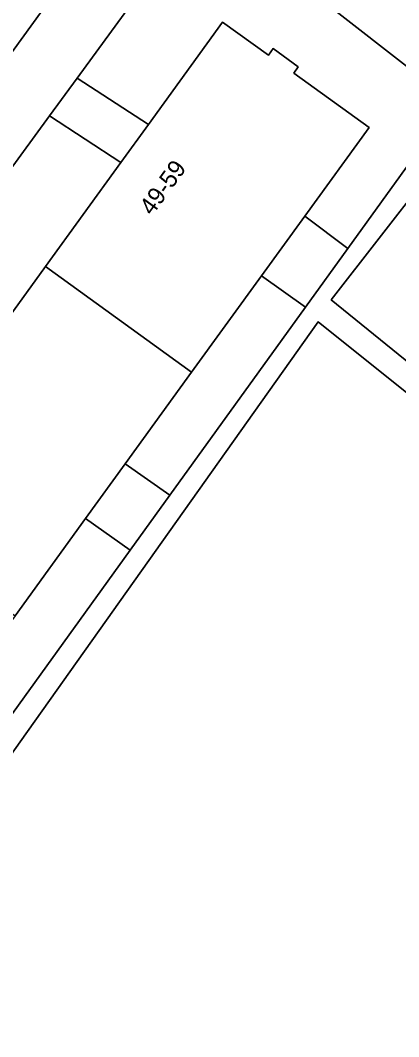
# Model space of a CAD drawing. Extents: x 160102 to 160934, y 382045 to 382923.
# Drawn here: x 160420.9 to 160442.6, y 382523.7 to 382582.2 of the extents above; entities that cross this region are included whole.
import ezdxf

# ---------------------------------------------------------------- set-up
doc = ezdxf.new("R2010")
doc.units = 0
for name, color, linetype in [('IMGEO_Groenvoorziening', 7, 'Continuous'), ('IMGEO_Pand', 7, 'Continuous'), ('IMGEO_Pand_nummerreeks', 7, 'Continuous'), ('IMGEO_Rijbaan_lokaal_open', 7, 'Continuous'), ('IMGEO_Voetpad_op_trap', 7, 'Continuous'), ('IMGEO_Voetpad_open', 7, 'Continuous')]:
    doc.layers.add(name, color=color, linetype=linetype)

msp = doc.modelspace()

# ---------------------------------------------------------------- linework, layer by layer
at = {"layer": 'IMGEO_Groenvoorziening'}
for points in [[(160430.115, 382587.054), (160424.126, 382578.857), (160428.223, 382576.184), (160432.492, 382582.073), (160435.12, 382580.168), (160435.4, 382580.554), (160436.844, 382579.507), (160436.581, 382579.143), (160440.91, 382576.005), (160437.214, 382570.907), (160439.693, 382569.052), (160445.752, 382577.45), (160433.113, 382587.311)], [(160472.07, 382537.55), (160437.989, 382564.836), (160403.791, 382516.657), (160410.005, 382512.232), (160410.556, 382511.838), (160413.843, 382516.2), (160417.933, 382521.84), (160420.393, 382520.056), (160422.852, 382518.273), (160425.312, 382516.489), (160427.772, 382514.705), (160430.232, 382512.922), (160432.692, 382511.138), (160435.152, 382509.354), (160437.611, 382507.571), (160440.071, 382505.787), (160442.541, 382503.996), (160439.632, 382500), (160438.441, 382498.363), (160435.401, 382494.048), (160435.774, 382493.781)]]:
    msp.add_lwpolyline(points, dxfattribs=at)
for points in [[(160448.284, 382571.507), (160448.623, 382571.236), (160450.605, 382573.72), (160456.375, 382569.115), (160459.072, 382572.243), (160450.852, 382578.804), (160448.152, 382575.578), (160446.881, 382576.57), (160438.73, 382566.096), (160447.552, 382558.944), (160449.558, 382561.251), (160444.105, 382565.604), (160447.497, 382569.854), (160447.172, 382570.113)], [(160426.646, 382574.008), (160422.539, 382576.683), (160413.97, 382564.954), (160418.113, 382562.237), (160422.306, 382568.021)], [(160437.257, 382565.676), (160434.732, 382567.482), (160430.709, 382561.932), (160426.893, 382556.667), (160429.461, 382554.871)], [(160427.176, 382551.704), (160424.614, 382553.524), (160420.556, 382547.925), (160416.873, 382542.845), (160419.461, 382541.01)]]:
    msp.add_lwpolyline(points, close=True, dxfattribs=at)
at = {"layer": 'IMGEO_Pand'}
for points in [[(160440.91, 382576.005), (160436.581, 382579.143), (160436.844, 382579.507), (160435.4, 382580.554), (160435.12, 382580.168), (160432.492, 382582.073), (160428.223, 382576.184), (160426.646, 382574.008), (160422.306, 382568.021), (160430.709, 382561.932), (160434.732, 382567.482), (160437.214, 382570.907)], [(160430.709, 382561.932), (160422.306, 382568.021), (160418.113, 382562.237), (160416.492, 382560), (160412.153, 382554.014), (160420.556, 382547.925), (160424.614, 382553.524), (160426.893, 382556.667)]]:
    msp.add_lwpolyline(points, close=True, dxfattribs=at)
at = {"layer": 'IMGEO_Rijbaan_lokaal_open'}
msp.add_lwpolyline([(160391.646, 382540.752), (160393.41, 382543.181), (160399.927, 382552.158), (160401.681, 382554.574), (160406.461, 382561.166), (160408.188, 382563.548), (160411.227, 382567.738), (160412.981, 382570.158), (160416.676, 382575.255), (160418.415, 382577.656), (160424.094, 382585.479), (160425.903, 382587.906), (160426.45, 382588.641), (160422.43, 382591.723), (160415.332, 382581.933), (160382.519, 382536.771), (160386.546, 382533.67)], close=True, dxfattribs=at)
at = {"layer": 'IMGEO_Voetpad_op_trap'}
for points in [[(160439.693, 382569.052), (160437.214, 382570.907), (160434.732, 382567.482), (160437.257, 382565.676)], [(160429.461, 382554.871), (160426.893, 382556.667), (160424.614, 382553.524), (160427.176, 382551.704)]]:
    msp.add_lwpolyline(points, close=True, dxfattribs=at)
at = {"layer": 'IMGEO_Voetpad_open'}
for points in [[(160402.258, 382548.922), (160403.833, 382551.078), (160412.434, 382562.851), (160413.97, 382564.954), (160422.539, 382576.683), (160424.126, 382578.857), (160430.115, 382587.054), (160435.406, 382595.933), (160432.912, 382597.37)], [(160433.113, 382587.311), (160445.752, 382577.45), (160446.881, 382576.57), (160448.152, 382575.578), (160450.852, 382578.804), (160459.072, 382572.243), (160461.271, 382570.488), (160472.502, 382561.524), (160474.597, 382559.852), (160480.93, 382554.797), (160484.046, 382558.32), (160483.799, 382558.523)], [(160424.094, 382585.479), (160418.415, 382577.656), (160419.887, 382576.604), (160418.163, 382574.192), (160416.676, 382575.255), (160412.981, 382570.158), (160414.463, 382569.08), (160412.705, 382566.663), (160411.227, 382567.738), (160408.188, 382563.548), (160409.648, 382562.496), (160407.928, 382560.109), (160406.461, 382561.166), (160401.681, 382554.574), (160403.149, 382553.526), (160401.414, 382551.096), (160399.927, 382552.158), (160393.41, 382543.181), (160394.877, 382542.108), (160393.106, 382539.685), (160391.646, 382540.752), (160386.546, 382533.67)], [(160445.752, 382577.45), (160439.693, 382569.052), (160437.257, 382565.676), (160429.461, 382554.871), (160427.176, 382551.704), (160419.461, 382541.01), (160417.265, 382537.967), (160409.286, 382526.908), (160407.104, 382523.884), (160403.7, 382519.166), (160402.184, 382517.802), (160403.791, 382516.657), (160437.989, 382564.836), (160472.07, 382537.55)], [(160447.552, 382558.944), (160438.73, 382566.096), (160446.881, 382576.57)]]:
    msp.add_lwpolyline(points, dxfattribs=at)
msp.add_lwpolyline([(160428.223, 382576.184), (160424.126, 382578.857), (160422.539, 382576.683), (160426.646, 382574.008)], close=True, dxfattribs=at)

# ---------------------------------------------------------------- texts
at = {"layer": 'IMGEO_Pand_nummerreeks'}
msp.add_text('49-59', height=1, rotation=54.0643, dxfattribs=at).set_placement((160428.441, 382570.896))

doc.saveas('drawing.dxf')
